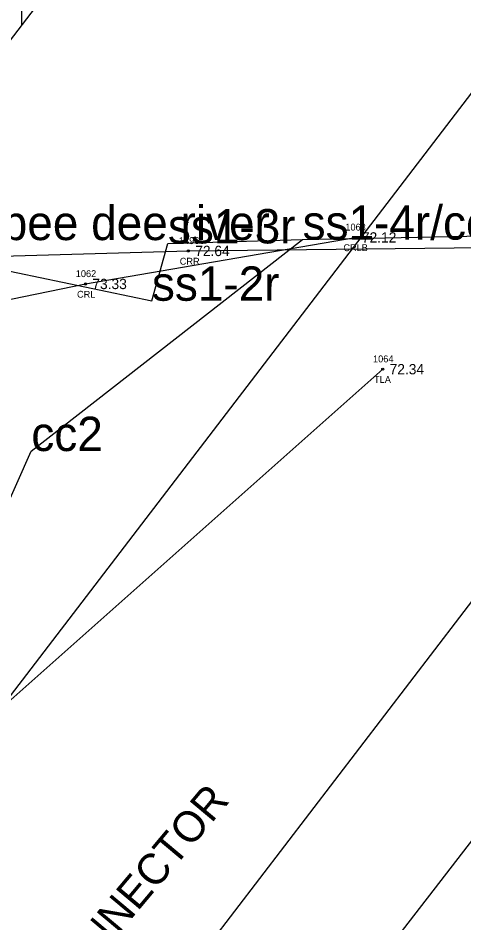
# Model space of a CAD drawing. Extents: x 2500794 to 2511032, y 910653 to 917533.
# Drawn here: x 2506079.6 to 2506144.5, y 913710.5 to 913842.2 of the extents above; entities that cross this region are included whole.
import ezdxf

# ---------------------------------------------------------------- set-up
doc = ezdxf.new("R2010")
doc.units = 0
for name, color, linetype in [('Default', 7, 'Continuous'), ('RD_EX_H2O', 7, 'Continuous'), ('RD_EX_H2O_txCode', 7, 'Continuous'), ('RD_EX_H2O_WetLd', 7, 'Continuous'), ('RD_EX_Misc', 7, 'Continuous'), ('RD_EX_RW', 7, 'Continuous'), ('RD_EX_TX_H2O_ELEV', 7, 'Continuous'), ('RD_EX_TX_VEG_ELEV', 7, 'Continuous'), ('RD_EX_VEG', 7, 'Continuous'), ('RD_EX_VEG_txCode', 7, 'Continuous'), ('RD_PD_Bridge', 7, 'Continuous'), ('RD_PD_MedBWall', 7, 'Continuous'), ('RD_Sketch9', 7, 'Continuous'), ('RD_SMD_Locator', 7, 'Continuous')]:
    doc.layers.add(name, color=color, linetype=linetype)

# ---------------------------------------------------------------- blocks, each defined once
blk = doc.blocks.new('POINT_DISPLAY')
at = {"layer": 'Default'}
blk.add_line((0, 0), (0, 0), dxfattribs=at)
blk = doc.blocks.new('Non-Wetland Waters (Tributaries)')
at = {"layer": 'Default'}
blk.add_lwpolyline([(636538.425, 232107.717), (636549.166, 232105.474), (636549.758, 232107.595), (636554.736, 232107.733), (636570.529, 232108.061), (636578.378, 232108.026)], dxfattribs=at)
blk = doc.blocks.new('Wetlands')
at = {"layer": 'Default'}
blk.add_lwpolyline([(636578.378, 232108.026), (636523.855, 232037.448), (636501.371, 232037.816), (636484.456, 232032.271), (636499.849, 232049.322), (636504.147, 232059.556), (636518.345, 232075.791), (636532.382, 232092.673), (636539.146, 232087.393), (636544.708, 232099.914), (636554.736, 232107.733), (636570.529, 232108.061), (636578.378, 232108.026)], dxfattribs=at)

msp = doc.modelspace()

# ---------------------------------------------------------------- linework, layer by layer
at = {"layer": 'RD_EX_H2O_txCode'}
for points in [[(2505644.45, 913807.58), (2505735.45, 913822.66), (2505800.85, 913818.32), (2505876.46, 913810.97), (2505914.87, 913815.81), (2505955.18, 913822.7), (2506003.2, 913816.23), (2506021.32, 913828.37), (2506028.84, 913826.12), (2506055.11, 913806.95), (2506104.38, 913808.33), (2506216.14, 913809.62), (2506311.29, 913789.92), (2506320.92, 913749.59), (2506242.37, 913648.56), (2506138.05, 913548.89)], [(2506050.33, 913797.99), (2506060.8, 913797.68), (2506089.41, 913803.52), (2506128.64, 913810.3)]]:
    msp.add_lwpolyline(points, dxfattribs=at)
at = {"layer": 'RD_EX_Misc'}
msp.add_line((2506080.17, 913841.09), (2506080.17, 913851.09), dxfattribs=at)
at = {"layer": 'RD_EX_RW'}
msp.add_line((2506073.83, 913737.47), (2506231.75, 913944.02), dxfattribs=at)
at = {"layer": 'RD_EX_VEG'}
msp.add_lwpolyline([(2506132.67, 913791.11), (2506063.24, 913729.37), (2505966.14, 913603.86), (2505918.37, 913544.18)], dxfattribs=at)
at = {"layer": 'RD_PD_Bridge'}
msp.add_line((2506034.1, 913781), (2506155.57, 913939.88), dxfattribs=at)
at = {"layer": 'RD_Sketch9'}
msp.add_line((2505975.42, 913534.66), (2506308.52, 913970.35), dxfattribs=at)
at = {"layer": 'RD_SMD_Locator'}
for centre in [(2506128.64, 913810.3), (2506104.38, 913808.33), (2506089.41, 913803.52), (2506132.67, 913791.11)]:
    msp.add_circle(centre, 0.15, dxfattribs=at)

# ---------------------------------------------------------------- block references
at = {"layer": 'Default', "xscale": 3.937007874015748, "yscale": 3.937007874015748}
for name, p in [('Wetlands', (0, 0)), ('Non-Wetland Waters (Tributaries)', (0, 0)), ('POINT_DISPLAY', (2506101.41, 913809.43)), ('POINT_DISPLAY', (2506101.41, 913809.43)), ('POINT_DISPLAY', (2506121.01, 913809.97)), ('POINT_DISPLAY', (2506121.01, 913809.97)), ('POINT_DISPLAY', (2506099.08, 913801.08)), ('POINT_DISPLAY', (2506099.08, 913801.08)), ('POINT_DISPLAY', (2506081.53, 913779.19)), ('POINT_DISPLAY', (2506081.53, 913779.19))]:
    msp.add_blockref(name, p, dxfattribs=at)
at = {"layer": 'RD_EX_H2O', "xscale": 3.937007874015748, "yscale": 3.937007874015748}
msp.add_blockref('Non-Wetland Waters (Tributaries)', (0, 0), dxfattribs=at)
at = {"layer": 'RD_EX_H2O_WetLd', "xscale": 3.937007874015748, "yscale": 3.937007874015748}
msp.add_blockref('Wetlands', (0, 0), dxfattribs=at)

# ---------------------------------------------------------------- texts
at = {"layer": 'Default'}
for s, p in [('ss1-1r/pee dee river', (2506056.79, 913809.91)), ('ss1-1r/pee dee river', (2506056.79, 913809.91)), ('ss1-3r', (2506101.41, 913809.43)), ('ss1-3r', (2506101.41, 913809.43)), ('ss1-4r/cc2', (2506121.01, 913809.97)), ('ss1-4r/cc2', (2506121.01, 913809.97)), ('ss1-2r', (2506099.08, 913801.08)), ('ss1-2r', (2506099.08, 913801.08)), ('cc2', (2506081.53, 913779.19)), ('cc2', (2506081.53, 913779.19))]:
    msp.add_text(s, height=5, dxfattribs=at).set_placement(p)
at = {"layer": 'RD_EX_H2O_txCode'}
for s, p in [('1063', (2506127.23, 913811.3)), ('1496', (2506103.01, 913809.33)), ('CRLB', (2506126.94, 913808.3)), ('CRR', (2506103.13, 913806.33)), ('1062', (2506088, 913804.52)), ('CRL', (2506088.18, 913801.52))]:
    msp.add_text(s, height=1, dxfattribs=at).set_placement(p)
at = {"layer": 'RD_EX_TX_H2O_ELEV'}
for s, p in [('72.12', (2506129.64, 913809.55)), ('72.64', (2506105.38, 913807.58)), ('73.33', (2506090.41, 913802.77))]:
    msp.add_text(s, height=1.5, dxfattribs=at).set_placement(p)
at = {"layer": 'RD_EX_TX_VEG_ELEV'}
msp.add_text('72.34', height=1.5, dxfattribs=at).set_placement((2506133.67, 913790.36))
at = {"layer": 'RD_EX_VEG_txCode'}
for s, p in [('1064', (2506131.26, 913792.11)), ('TLA', (2506131.41, 913789.11))]:
    msp.add_text(s, height=1, dxfattribs=at).set_placement(p)
at = {"layer": 'RD_PD_MedBWall'}
msp.add_text('CONSTRUCT  2 THRIE BEAM BRIDGE CONNECTOR', height=4.5, rotation=50.0195, dxfattribs=at).set_placement((2506015.36, 913614.73))

doc.saveas('drawing.dxf')
